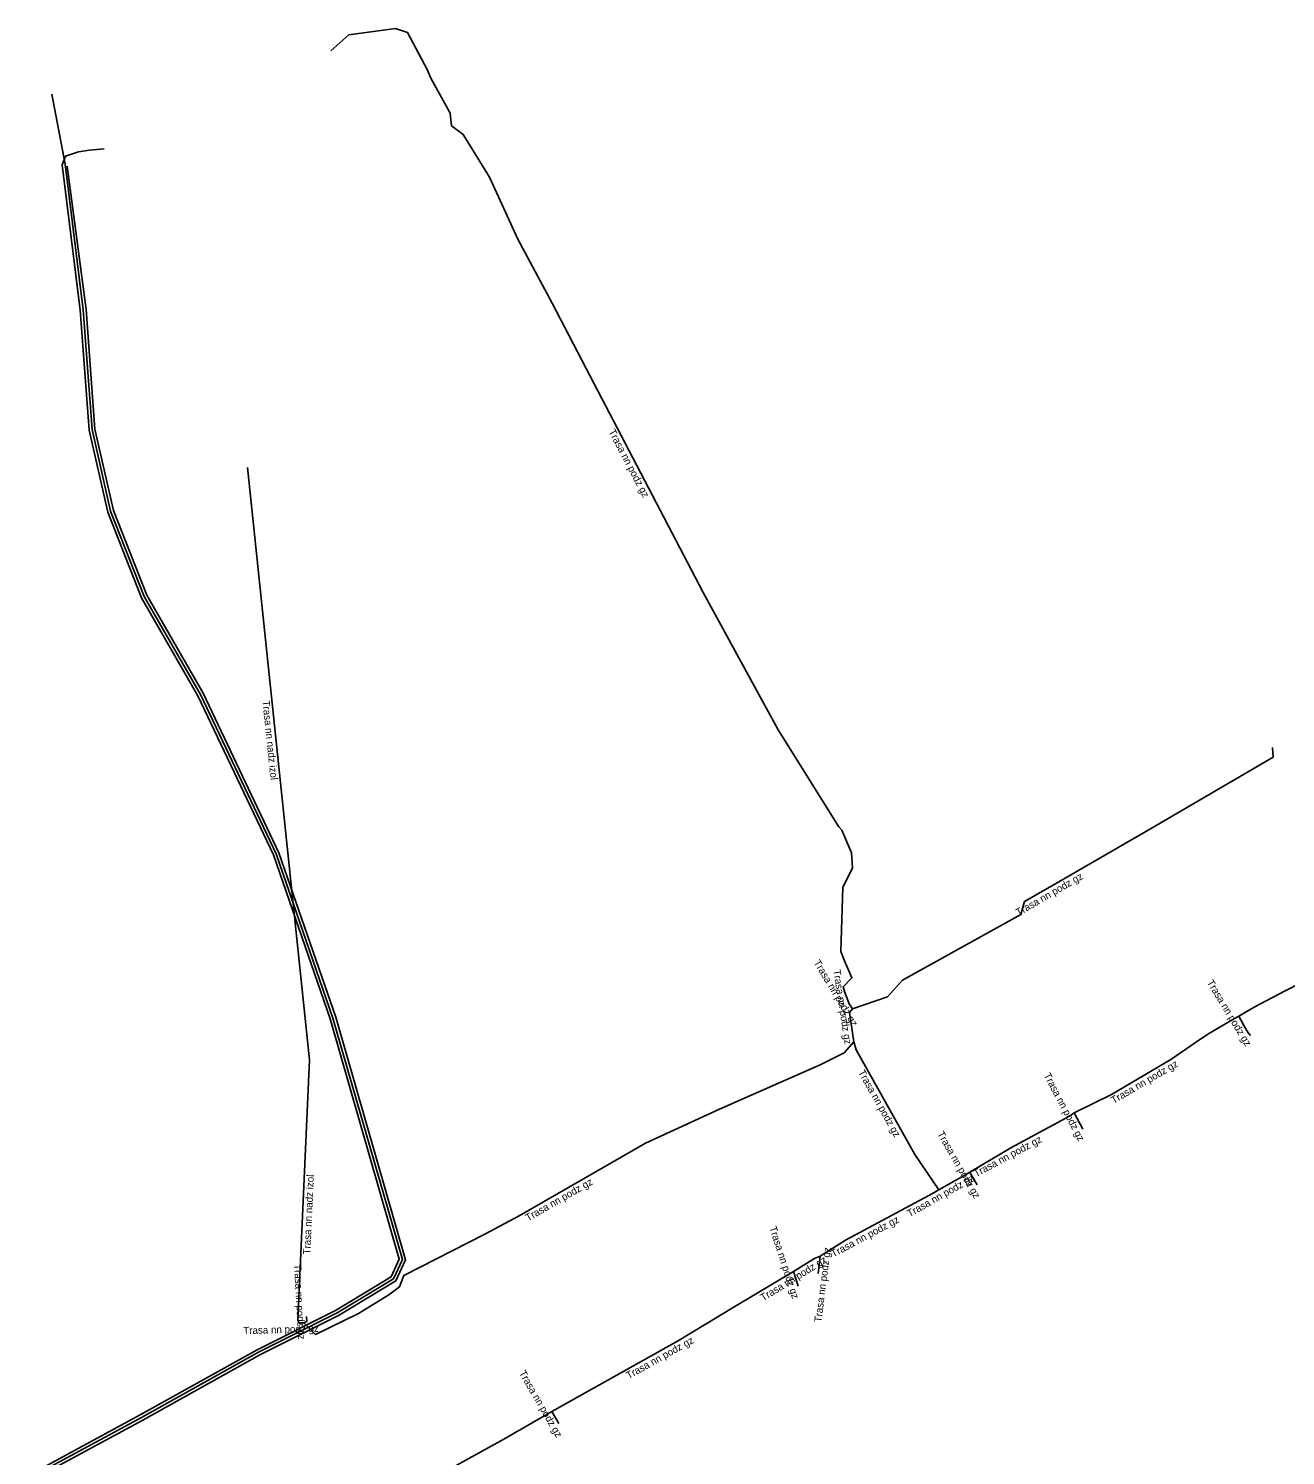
# Model space of a CAD drawing. Extents: x -687924 to -686708, y -1056742 to -1056249.
# Drawn here: x -687467 to -687381, y -1056514.3 to -1056416.7 of the extents above; entities that cross this region are included whole.
import ezdxf

# ---------------------------------------------------------------- set-up
doc = ezdxf.new("R2010")
doc.units = 0
for name, color, linetype in [('Popiskový text - Ostatní atributy Trasy', 7, 'Continuous'), ('Spojnice NN', 7, 'Continuous'), ('Spojnice VN', 7, 'Continuous')]:
    doc.layers.add(name, color=color, linetype=linetype)

msp = doc.modelspace()

# ---------------------------------------------------------------- linework, layer by layer
at = {"layer": 'Spojnice NN'}
for points in [[(-687410.86, -1056483.39), (-687411.18, -1056482.54), (-687411.28, -1056482.22), (-687410.68, -1056481.61), (-687411.19, -1056480.44), (-687411.44, -1056479.8), (-687411.29, -1056475.42), (-687410.65, -1056474.12), (-687410.71, -1056473.07), (-687411.36, -1056471.52), (-687411.58, -1056471.29), (-687415.73, -1056464.64), (-687420.85, -1056455.25), (-687428.86, -1056439.94), (-687431.19, -1056435.47), (-687433.54, -1056431.1), (-687435.46, -1056426.86), (-687437.27, -1056423.93), (-687438.07, -1056423.34), (-687438.17, -1056422.47), (-687439.49, -1056420.09), (-687439.74, -1056419.48), (-687441.09, -1056416.97), (-687441.9, -1056416.69), (-687445.1, -1056417.12), (-687446.324, -1056418.222)], [(-687452.03, -1056446.71), (-687447.78, -1056487.22)], [(-687410.65, -1056483.74), (-687408.24, -1056482.92), (-687407.21, -1056481.76), (-687399.13, -1056477.28), (-687398.88, -1056476.39), (-687396.53, -1056475.05), (-687390.13, -1056471.34), (-687381.86, -1056466.51), (-687381.9, -1056465.86)], [(-687369.43, -1056476.35), (-687369.93, -1056476.55), (-687372.56, -1056477.94), (-687375.68, -1056479.77), (-687378.76, -1056481.34), (-687381.05, -1056482.5), (-687383.17, -1056483.62), (-687384.21, -1056484.24)], [(-687410.86, -1056483.39), (-687410.65, -1056483.74)], [(-687410.54, -1056485.99), (-687410.85, -1056483.99), (-687410.65, -1056483.74)], [(-687384.21, -1056484.24), (-687384.51, -1056484.38), (-687386.33, -1056485.47), (-687387.18, -1056486.04), (-687388.87, -1056487.2), (-687392.93, -1056489.58), (-687395.48, -1056490.85)], [(-687384.21, -1056484.24), (-687383.9, -1056484.83), (-687383.58, -1056485.36), (-687383.42, -1056485.56)], [(-687448.18, -1056505.2), (-687447.38, -1056505.99), (-687444.44, -1056504.56), (-687442.36, -1056503.28), (-687441.62, -1056502.73), (-687441.33, -1056501.97), (-687435.78, -1056499.15), (-687433.45, -1056497.88), (-687424.81, -1056492.92), (-687419.74, -1056490.59), (-687412.84, -1056487.57), (-687411.2, -1056486.74), (-687410.54, -1056485.99)], [(-687410.54, -1056485.99), (-687410.38, -1056486.53), (-687406.38, -1056493.68), (-687404.73, -1056496.11)], [(-687447.78, -1056487.22), (-687448.58, -1056505.02)], [(-687395.48, -1056490.85), (-687395.79, -1056491.07), (-687399.8, -1056493.23), (-687402.61, -1056494.89)], [(-687395.48, -1056490.85), (-687394.89, -1056491.97)], [(-687402.61, -1056494.89), (-687402.84, -1056495.04), (-687404.73, -1056496.11)], [(-687402.61, -1056494.89), (-687402.47, -1056495.14), (-687402.11, -1056495.77)], [(-687404.73, -1056496.11), (-687405.41, -1056496.49), (-687411.12, -1056499.56), (-687412.85, -1056500.65)], [(-687412.85, -1056500.65), (-687413.24, -1056500.81), (-687414.68, -1056501.7)], [(-687412.85, -1056500.65), (-687412.95, -1056501.44), (-687412.99, -1056501.84)], [(-687414.68, -1056501.7), (-687418.69, -1056504.08), (-687422.61, -1056506.45), (-687431.2, -1056511.26)], [(-687414.68, -1056501.7), (-687414.36, -1056502.69)], [(-687448.18, -1056505.2), (-687447.97, -1056505.11), (-687447.99, -1056504.76)], [(-687448.58, -1056505.02), (-687448.48, -1056505.21), (-687448.18, -1056505.2)], [(-687431.2, -1056511.26), (-687434.49, -1056513.15), (-687441.68, -1056517.13), (-687447.52, -1056520.36)], [(-687431.2, -1056511.26), (-687430.72, -1056512.09)]]:
    msp.add_lwpolyline(points, dxfattribs=at)
at = {"layer": 'Spojnice VN'}
for points in [[(-687466.91, -1056515.81), (-687459.27, -1056511.68), (-687451.28, -1056507.22), (-687445.9, -1056504.53), (-687442.04, -1056502.19), (-687441.43, -1056500.87), (-687446.18, -1056484.36), (-687450.07, -1056473.13), (-687455.24, -1056462.24), (-687459.1, -1056455.53), (-687461.39, -1056449.7), (-687462.66, -1056444.12), (-687463.27, -1056435.93), (-687464.5, -1056425.97), (-687465.42, -1056421.18)], [(-687461.84, -1056424.91), (-687462.841, -1056425.002), (-687463.59, -1056425.13), (-687464.469, -1056425.418), (-687464.698, -1056426.001), (-687463.469, -1056435.95), (-687462.858, -1056444.15), (-687461.582, -1056449.759), (-687459.281, -1056455.617), (-687455.417, -1056462.333), (-687450.255, -1056473.206), (-687446.371, -1056484.42), (-687441.643, -1056500.854), (-687442.196, -1056502.051), (-687445.997, -1056504.355), (-687451.374, -1056507.043), (-687459.366, -1056511.505), (-687467.004, -1056515.634)], [(-687466.816, -1056515.986), (-687459.174, -1056511.855), (-687451.186, -1056507.397), (-687445.803, -1056504.705), (-687441.884, -1056502.329), (-687441.217, -1056500.886), (-687445.989, -1056484.3), (-687449.885, -1056473.054), (-687455.063, -1056462.147), (-687458.919, -1056455.443), (-687461.198, -1056449.641), (-687462.462, -1056444.09), (-687463.071, -1056435.91), (-687464.37, -1056426.1)]]:
    msp.add_lwpolyline(points, dxfattribs=at)

# ---------------------------------------------------------------- texts
at = {"layer": 'Popiskový text - Ostatní atributy Trasy'}
for s, rotation, p in [('Trasa nn podz gz', 297.618, (-687427.342, -1056444.245)), ('Trasa nn nadz izol', 275.98913, (-687451.01, -1056462.667)), ('Trasa nn podz gz', 30.10033, (-687399.287, -1056477.399)), ('Trasa nn podz gz', 300.96376, (-687413.316, -1056480.561)), ('Trasa nn podz gz', 278.81073, (-687411.958, -1056481.084)), ('Trasa nn podz gz', 301.12247, (-687386.415, -1056481.922)), ('Trasa nn podz gz', 299.22442, (-687410.269, -1056488.06)), ('Trasa nn podz gz', 297.77962, (-687397.575, -1056488.268)), ('Trasa nn podz gz', 30.37913, (-687392.776, -1056490.243)), ('Trasa nn podz gz', 299.74488, (-687404.857, -1056492.272)), ('Trasa nn podz gz', 28.30928, (-687402.184, -1056495.253)), ('Trasa nn nadz izol', 87.42664, (-687447.727, -1056500.535)), ('Trasa nn podz gz', 29.85902, (-687432.834, -1056498.276)), ('Trasa nn podz gz', 29.51583, (-687406.733, -1056497.991)), ('Trasa nn podz gz', 28.26484, (-687411.944, -1056500.741)), ('Trasa nn podz gz', 287.91251, (-687416.336, -1056498.69)), ('Trasa nn podz gz', 31.71837, (-687416.751, -1056503.744)), ('Trasa nn podz gz', 82.78574, (-687412.769, -1056505.189)), ('Trasa nn podz gz', 273.27049, (-687448.845, -1056501.199)), ('Trasa nn podz gz', 1.90915, (-687452.307, -1056505.988)), ('Trasa nn podz gz', 29.2468, (-687425.952, -1056509.066)), ('Trasa nn podz gz', 300.04136, (-687433.472, -1056508.63))]:
    msp.add_text(s, height=0.5, rotation=rotation, dxfattribs=at).set_placement(p)

doc.saveas('drawing.dxf')
